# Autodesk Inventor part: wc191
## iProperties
Shininess: 64.0
Length Units: 11272
Angle Units: 11279
Time Units: 11290
Mass Units: 11286
Length Display Precision: 3
Angle Display Precision: 2
Compacted: True
Part Number: wc191
Document SubType Name: Modeling
Created: 2004-08
Designer: John Blackburn
Manufacturer: Standard
Standards Organization: Custom
Material: Phenolic
Density: 0.0
Volumn: 0.0
Area: 0.0
PropertySet Name: Model Information
Control State: 0
Master: False
Checked Out: False
Author: John Blackburn
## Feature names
1. Base1
